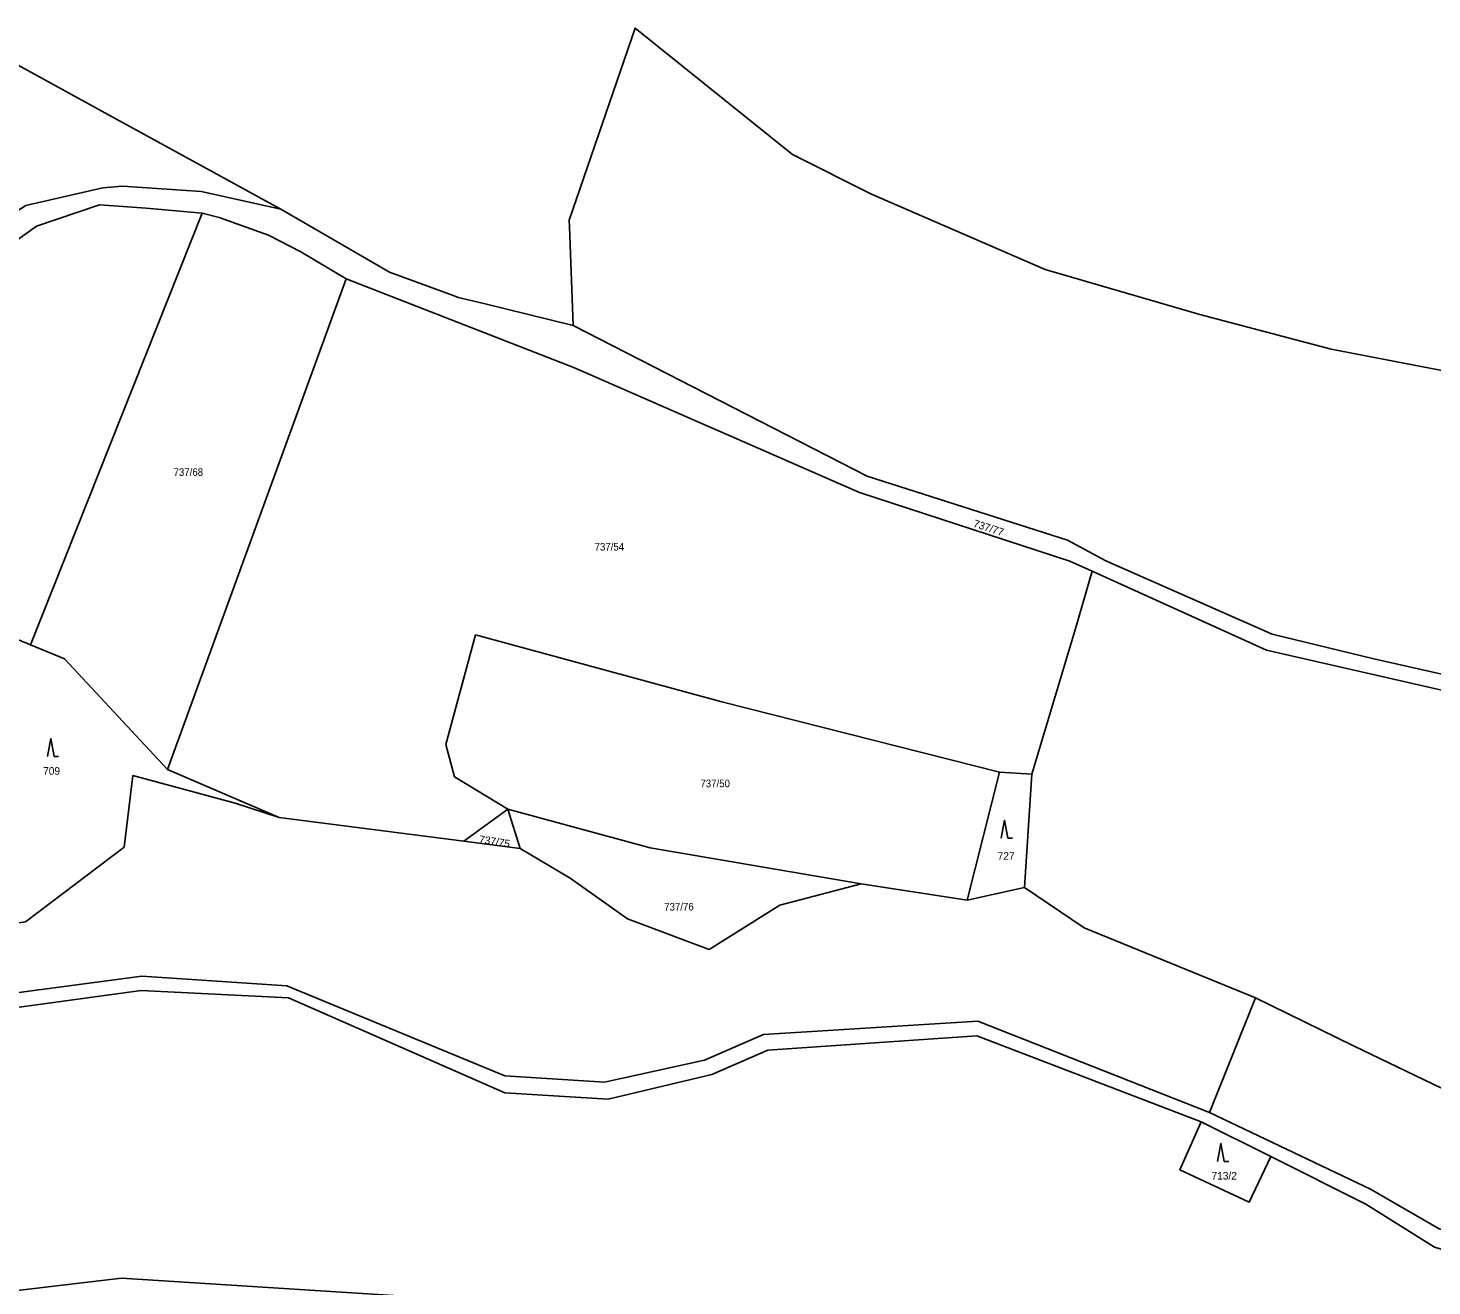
# Model space of a CAD drawing. Extents: x -687135 to -684370, y -1007309 to -1005782.
# Drawn here: x -686141.1 to -685826.9, y -1006769.6 to -1006488 of the extents above; entities that cross this region are included whole.
import ezdxf

# ---------------------------------------------------------------- set-up
doc = ezdxf.new("R2010")
doc.units = 0
doc.header["$LTSCALE"] = 0.68
doc.layers.add('1', color=7, linetype='Continuous', lineweight=25)
doc.layers.add('3', color=7, linetype='Continuous', lineweight=25)
doc.layers.add('2', color=7, linetype='Continuous')

msp = doc.modelspace()

# ---------------------------------------------------------------- linework, layer by layer
at = {"layer": '1'}
for p, q in [((-686093.28, -1006523.76), (-686124.64, -1006506.61)), ((-686140.6, -1006626.09), (-686102.13, -1006529.45)), ((-686019.08, -1006554.64), (-686019.95, -1006532.52)), ((-686039.12, -1006549.71), (-686019.08, -1006554.64)), ((-686084.96, -1006664.73), (-686109.9, -1006654.03)), ((-685923.68, -1006654.62), (-685930.92, -1006683.29)), ((-686043.56, -1006670.05), (-686033.74, -1006662.87)), ((-686030.96, -1006671.67), (-686033.74, -1006662.87)), ((-685862.91, -1006740.67), (-685878.5, -1006732.89))]:
    msp.add_line(p, q, dxfattribs=at)
for points in [[(-686166.37, -1006488.85), (-686144.21, -1006495.9), (-686124.64, -1006506.61)], [(-685608.88, -1006566.69), (-685634.62, -1006574.86), (-685679.01, -1006578.9), (-685733.36, -1006577.22), (-685801, -1006569.26), (-685849.41, -1006559.88), (-685878.83, -1006552.16), (-685913.42, -1006542.07), (-685952.34, -1006525.21), (-685970.01, -1006516.36), (-686005.23, -1006488.02), (-686020.01, -1006531.02), (-686019.95, -1006532.52)], [(-686165.61, -1006543.15), (-686141.63, -1006527.76), (-686124.38, -1006523.77), (-686119.97, -1006523.43), (-686102.38, -1006524.64), (-686084.53, -1006528.55), (-686087.98, -1006526.66), (-686093.28, -1006523.76)], [(-686102.13, -1006529.45), (-686114.72, -1006528.31), (-686125.17, -1006527.56), (-686139.22, -1006532.34), (-686164.52, -1006550.47)], [(-686069.95, -1006544.16), (-686080.11, -1006538.14), (-686087.28, -1006534.36), (-686098.36, -1006530.45), (-686102.13, -1006529.45)], [(-686039.12, -1006549.71), (-686044.84, -1006548.3), (-686045.78, -1006547.96), (-686060.2, -1006542.69), (-686084.53, -1006528.55)], [(-685902.96, -1006609.62), (-685907.91, -1006607.35), (-685955.01, -1006591.96), (-686018.83, -1006564.05), (-686069.95, -1006544.16), (-686109.9, -1006654.03)], [(-686019.08, -1006554.64), (-685953.3, -1006588.31), (-685908.41, -1006602.66), (-685899.85, -1006607.32), (-685862.63, -1006623.68), (-685839.89, -1006629.21), (-685806.41, -1006636.76), (-685782.11, -1006639.91), (-685731.95, -1006645.69), (-685708.06, -1006650.1), (-685686.69, -1006652.24), (-685672.41, -1006649.09)], [(-685878.5, -1006732.89), (-685928.73, -1006713.6), (-685975.55, -1006716.87), (-685988.08, -1006722.32), (-686011.25, -1006727.78), (-686034.41, -1006726.41), (-686082.84, -1006705.15), (-686115.81, -1006703.51), (-686202.12, -1006715.24), (-686241.64, -1006713.33), (-686262.35, -1006721.24), (-686330.66, -1006718.97), (-686386.9, -1006713.77), (-686422.4, -1006720.35), (-686454.83, -1006714.05), (-686546.04, -1006658.04), (-686579.08, -1006621.42), (-686600.54, -1006604.47), (-686642.63, -1006556.52)], [(-685916.44, -1006655.07), (-685906.57, -1006622.2), (-685902.96, -1006609.62)], [(-685902.96, -1006609.62), (-685863.86, -1006627.32), (-685810.59, -1006639.46), (-685794.4, -1006641.53), (-685734.22, -1006648.98), (-685705.31, -1006654.75)], [(-686109.9, -1006654.03), (-686132.98, -1006629.22), (-686140.6, -1006626.09), (-686160.31, -1006617.98), (-686164.6, -1006621.5), (-686165.98, -1006622.63)], [(-685923.68, -1006654.62), (-685985.85, -1006638.83), (-686040.96, -1006623.87), (-686047.65, -1006648.42), (-686045.68, -1006655.64), (-686033.74, -1006662.87)], [(-686084.96, -1006664.73), (-686094.77, -1006661.56), (-686117.7, -1006655.37), (-686119.66, -1006671.37), (-686141.68, -1006688.12), (-686162.53, -1006691.14)], [(-685918.1, -1006680.42), (-685916.44, -1006655.07), (-685923.68, -1006654.62)], [(-685954.61, -1006679.63), (-685972.88, -1006684.35), (-685988.7, -1006694.3), (-686006.94, -1006687.41), (-686019.8, -1006678.31), (-686030.96, -1006671.67), (-686043.56, -1006670.05), (-686084.96, -1006664.73)], [(-686033.74, -1006662.87), (-686001.84, -1006671.53), (-685954.61, -1006679.63)], [(-685876.62, -1006730.81), (-685840.65, -1006747.95), (-685825.24, -1006756.86), (-685802.11, -1006763.88), (-685757.92, -1006761.14), (-685685.53, -1006732.35), (-685670.46, -1006714.87), (-685661.89, -1006678.2), (-685660.21, -1006670.08)], [(-685866.37, -1006705.16), (-685904.68, -1006689.47), (-685918.1, -1006680.42), (-685930.92, -1006683.29), (-685954.61, -1006679.63)], [(-685669.25, -1006683.97), (-685668.16, -1006697.46), (-685676.45, -1006715.56), (-685699.23, -1006726.7), (-685721.43, -1006726.36), (-685762.88, -1006745.55), (-685789.43, -1006741.26), (-685804.85, -1006734.92), (-685844.42, -1006715.9), (-685866.37, -1006705.16)], [(-686148.89, -1006704.67), (-686115.65, -1006700.25), (-686083.22, -1006702.43), (-686034.44, -1006722.6), (-686012.09, -1006723.97), (-685989.74, -1006719.06), (-685976.47, -1006713.34), (-685928.51, -1006710.34), (-685876.62, -1006730.81), (-685866.37, -1006705.16)], [(-685862.91, -1006740.67), (-685867.74, -1006750.85), (-685883.33, -1006743.61), (-685878.5, -1006732.89)], [(-685789.93, -1006767.93), (-685804.25, -1006767.45), (-685826.27, -1006760.94), (-685841.68, -1006751.35), (-685862.91, -1006740.67)], [(-686343.59, -1006806.28), (-686314.7, -1006796.2), (-686276.55, -1006786.38), (-686120.2, -1006767.85), (-686044, -1006772.76), (-685931.45, -1006773.3), (-685897.9, -1006785.97), (-685807.25, -1006786.78), (-685789.93, -1006767.93)]]:
    msp.add_lwpolyline(points, dxfattribs=at)
at = {"layer": '3'}
for p, q in [((-686135.3, -1006651.09), (-686134.304, -1006651.09)), ((-685921.77, -1006669.35), (-685920.774, -1006669.35)), ((-685873.36, -1006741.73), (-685872.364, -1006741.73))]:
    msp.add_line(p, q, dxfattribs=at)
for points in [[(-686135.3, -1006651.09), (-686136.05, -1006647.09), (-686136.8, -1006651.09)], [(-685921.77, -1006669.35), (-685922.52, -1006665.35), (-685923.27, -1006669.35)], [(-685873.36, -1006741.73), (-685874.11, -1006737.73), (-685874.86, -1006741.73)]]:
    msp.add_lwpolyline(points, dxfattribs=at)

# ---------------------------------------------------------------- texts
at = {"layer": '2', "width": 0.95}
for s, p in [('737/68', (-686108.57, -1006588.27)), ('737/54', (-686014.31, -1006604.99)), ('737/50', (-685990.62, -1006657.98)), ('737/76', (-685998.73, -1006685.58))]:
    msp.add_text(s, height=1.7, dxfattribs=at).set_placement(p)
at = {"layer": '2'}
for s, rotation, p in [('737/77', 342, (-685929.662, -1006599.638)), ('737/75', 351, (-686040.282, -1006670.419))]:
    msp.add_text(s, height=1.7, rotation=rotation, dxfattribs=at).set_placement(p)
for s, p in [('709', (-686137.77, -1006655.179)), ('727', (-685924.09, -1006674.22)), ('713/2', (-685876.21, -1006745.799))]:
    msp.add_text(s, height=1.7, dxfattribs=at).set_placement(p)

doc.saveas('drawing.dxf')
